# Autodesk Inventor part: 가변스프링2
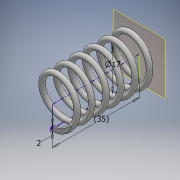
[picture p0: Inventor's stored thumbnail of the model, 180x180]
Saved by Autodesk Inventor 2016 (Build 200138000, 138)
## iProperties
Created: 2021-02
Part Number: 가변스프링2
Material: 일반
Document SubType Name: Modeling
Designer: Windows7
Density: 1 g/cm^3
Appearance: 기본값
Mass: 0.990408 g
Surface Area: 20.0926 cm^2
Volume: 0.990408 cm^3
Author: Windows7
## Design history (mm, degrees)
sketch "스케치1"
  geometry: L1 (0, 0)-(26.33, 0); L2 (26.33, 0)-(26.33, -8.5); L3 (26.33, -8.5)-(0, -8.5); L4 (0, -8.5)-(0, 0); C1 r 1 at (0, -8.5)
  constraints: 8 end point, 2 parallel, 1 centre point, 1 coincident, 1 horizontal, 1 perpendicular
  dimensions: "d0" = 2 diameter of C1; "d1" = 17 diameter of L3 L1; "d2" = 26.33013 distance of L2.end L3.end (derived)
feature "코일1" pitch "d3" = 10; turns "d5" = 6; dims "d4" = 26.33013 (= d2), "d6" = 0, angle "d7" = 90 deg, angle "d8" = 90 deg, "d9" = 0, "d10" = 0
feature "분할1"
node "작업 평면1"
feature "분할2"
node "솔리드1"
other parameters: "d11" = 90 deg
